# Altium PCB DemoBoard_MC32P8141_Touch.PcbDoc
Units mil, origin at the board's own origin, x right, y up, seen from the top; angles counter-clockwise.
Board outline 4235 x 4095 mil, 2 copper layers (Top Layer, Bottom Layer); 32 components, 31 nets, 87 pads, 28 vias.
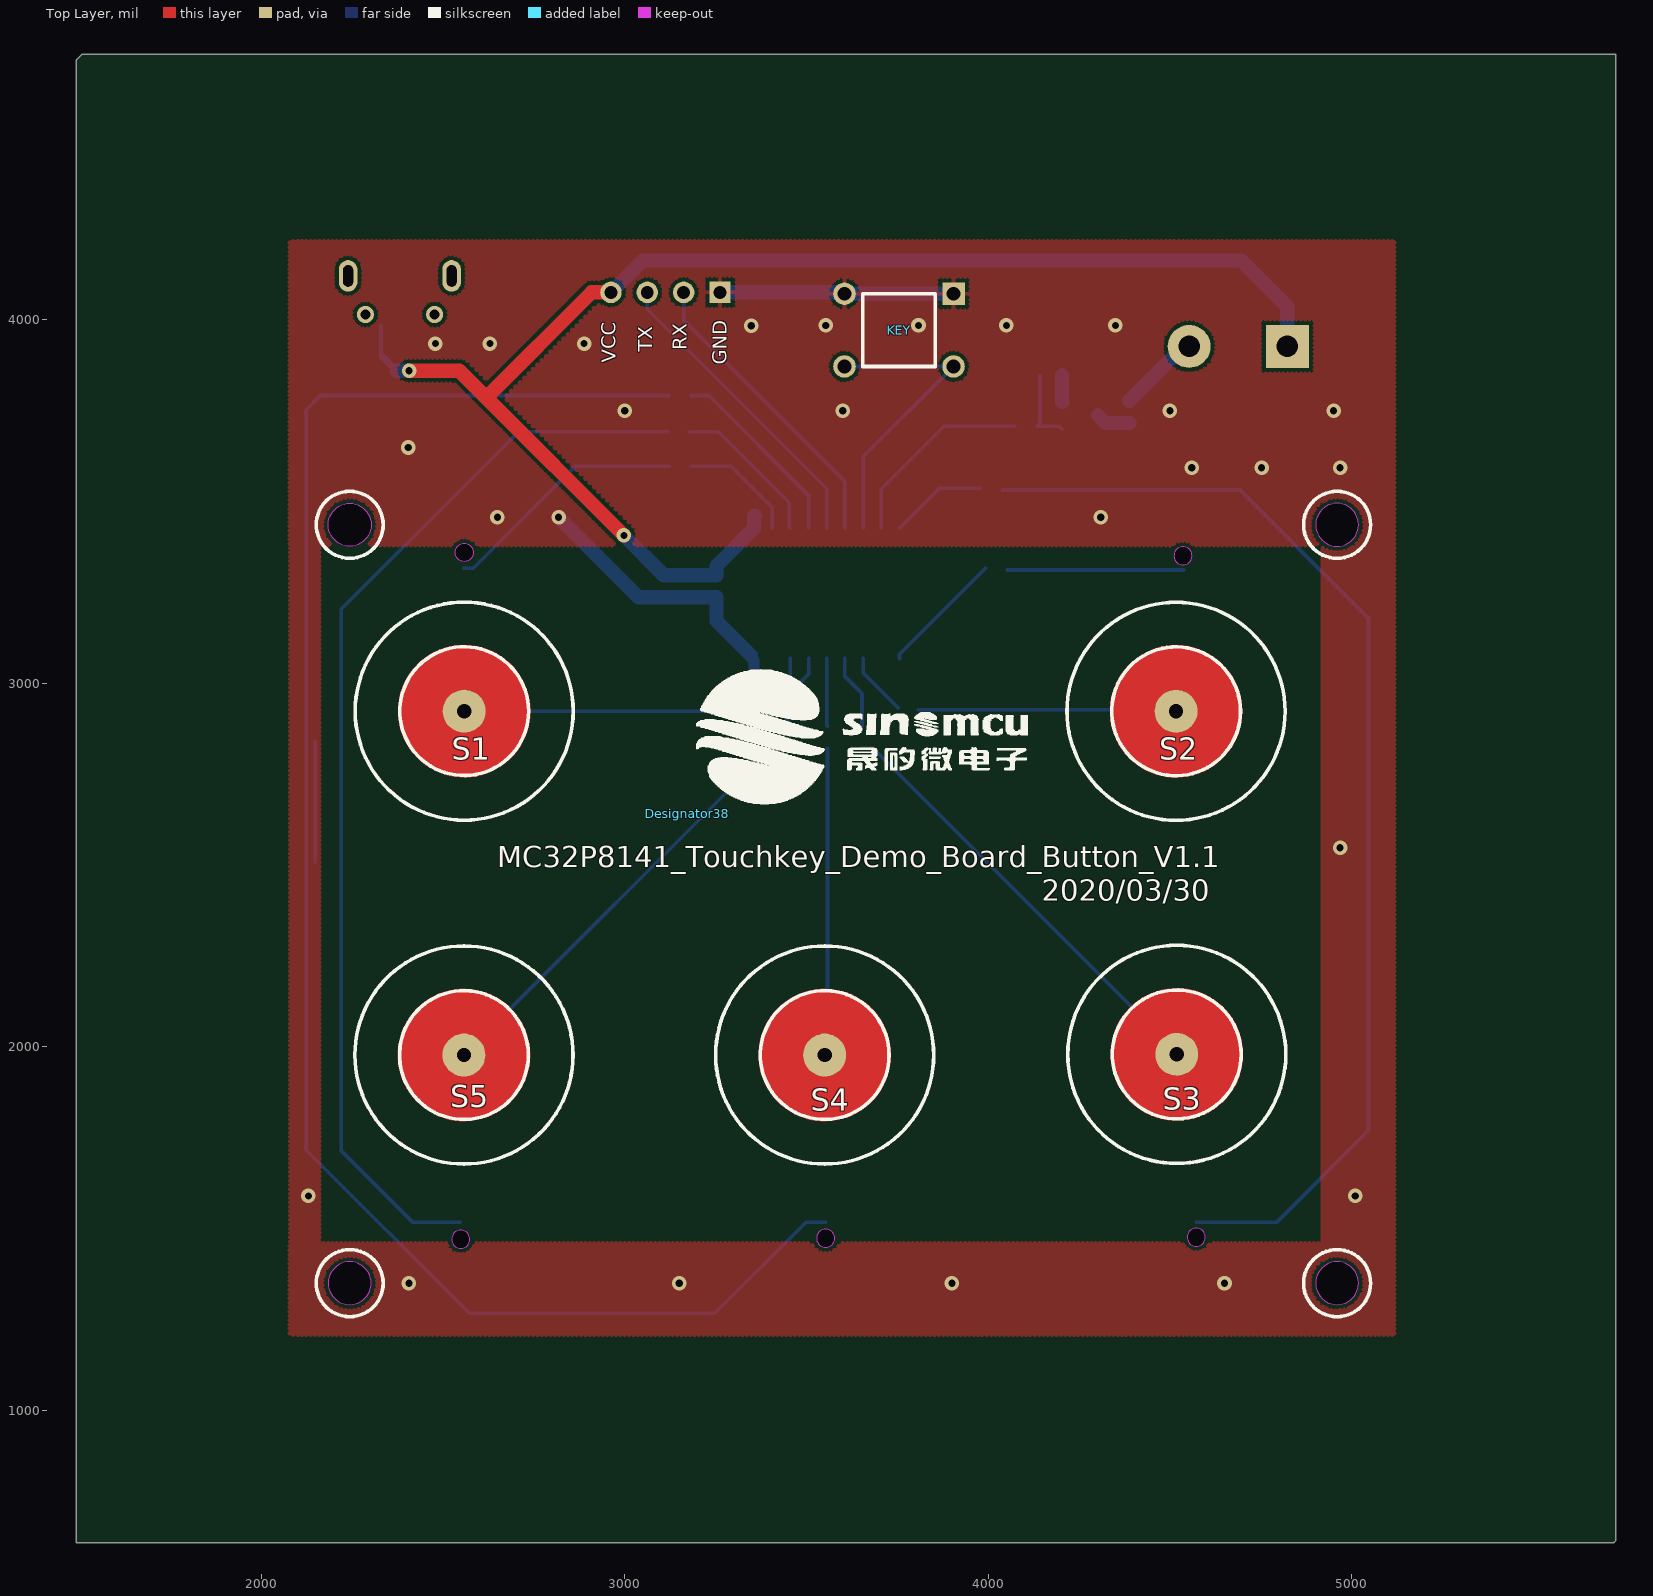
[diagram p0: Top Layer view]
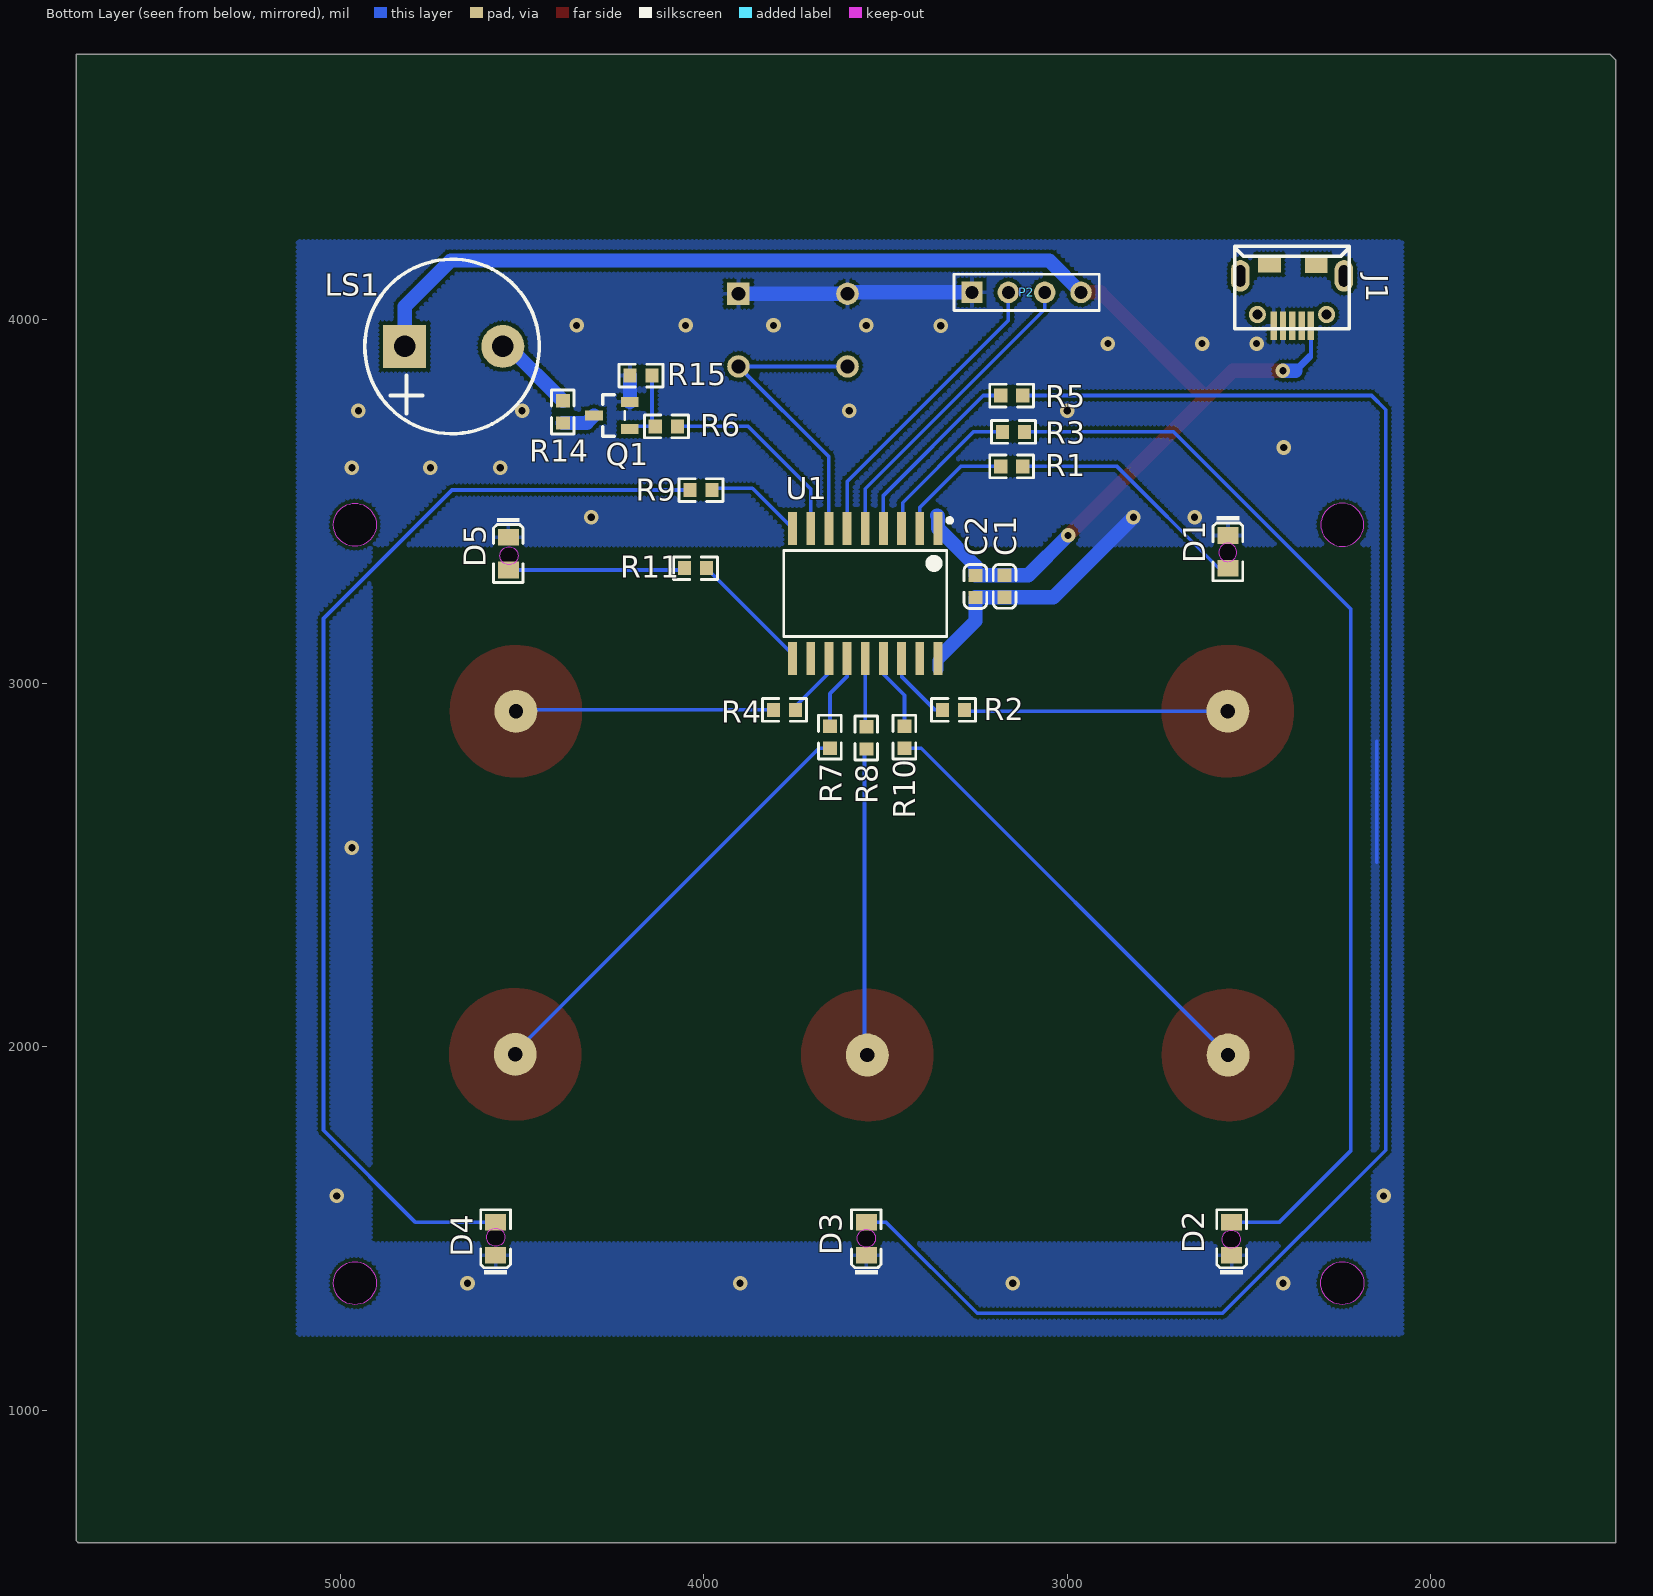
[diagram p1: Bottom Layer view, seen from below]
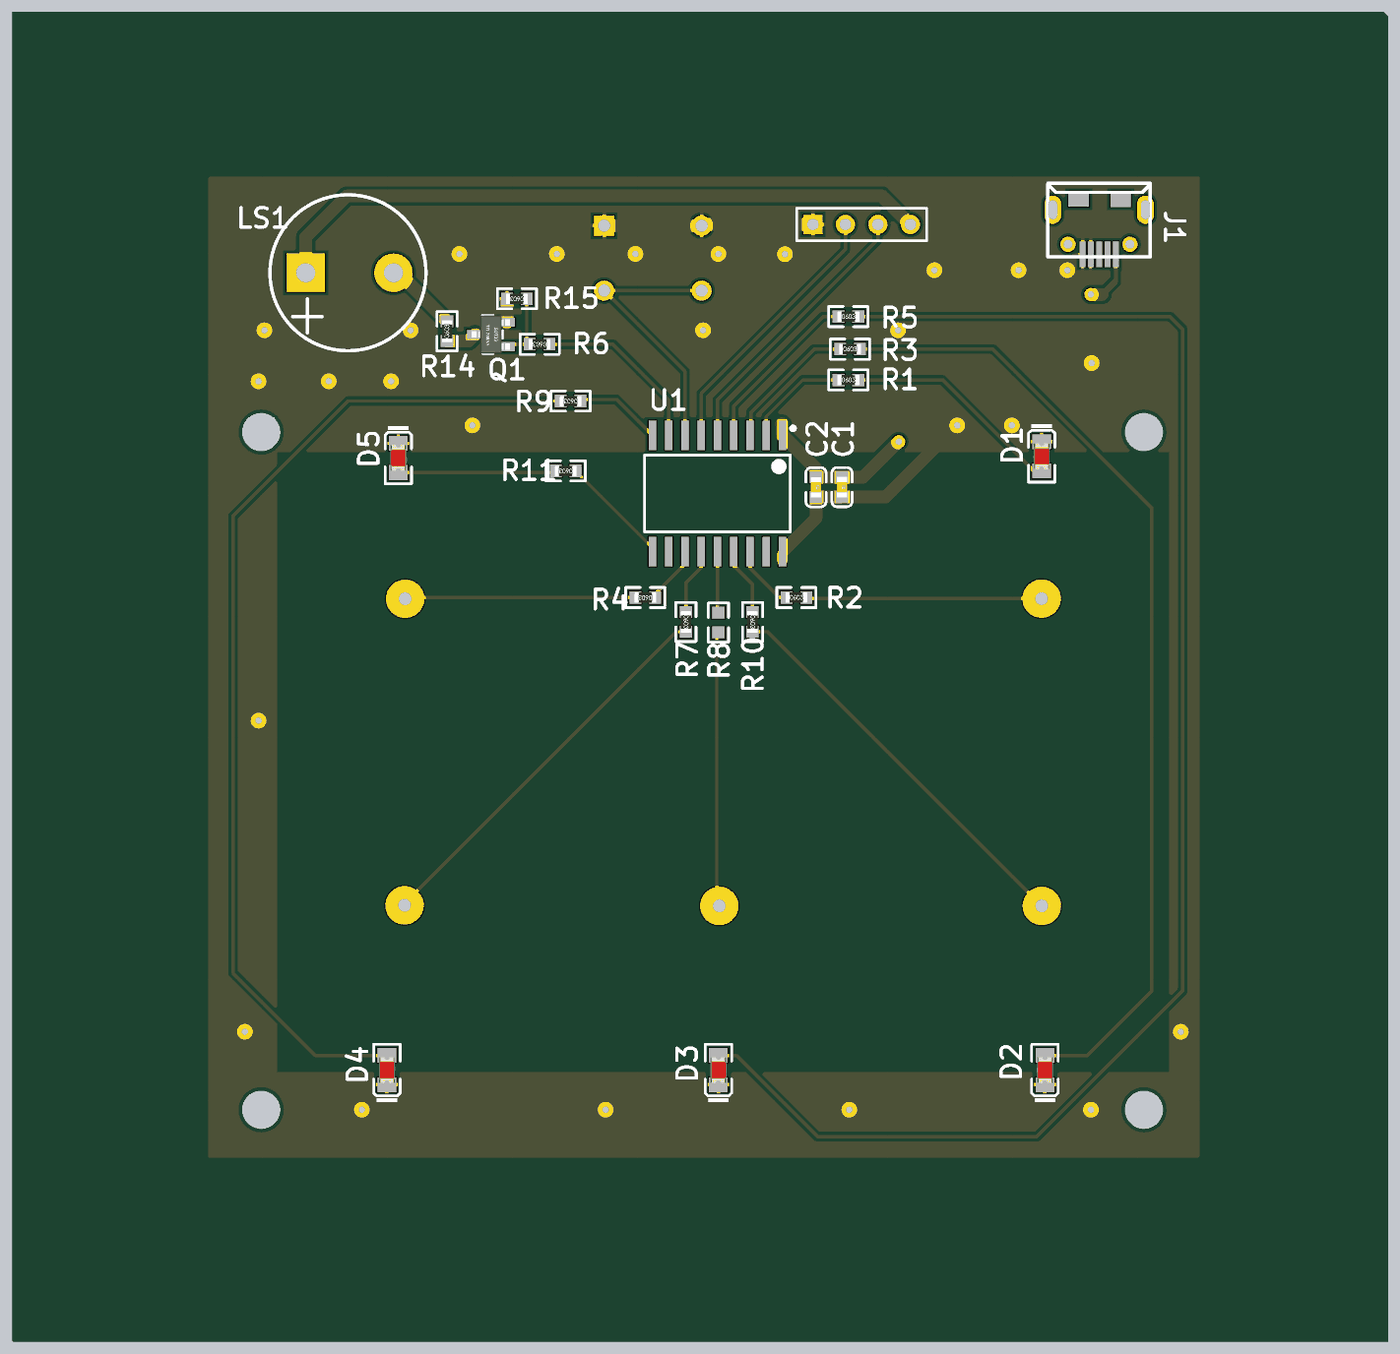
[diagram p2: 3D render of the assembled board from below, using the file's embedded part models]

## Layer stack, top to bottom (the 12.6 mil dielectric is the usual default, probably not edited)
Top Layer: signal copper 1.4
Dielectric: dielectric 12.6, FR-4, Dk 4.8
Bottom Layer: signal copper 1.4

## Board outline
5726.18,4730.67 5726.18,640.67 5721.18,635.67 1491.18,635.67 1491.18,4715.67 1506.18,4730.67
cut-out: 4900.79,3436.42 ccw(c4959.84,3436.42) 4959.84,3377.36 ccw(c4959.84,3436.42) 5018.9,3436.42 ccw(c4959.84,3436.42) 4959.84,3495.47 ccw(c4959.84,3436.42)
cut-out: 4900.79,1349.8 ccw(c4959.84,1349.8) 4959.84,1290.75 ccw(c4959.84,1349.8) 5018.9,1349.8 ccw(c4959.84,1349.8) 4959.84,1408.86 ccw(c4959.84,1349.8)
cut-out: 2523.62,1470.47 ccw(c2548.62,1470.47) 2548.62,1445.47 ccw(c2548.62,1470.47) 2573.62,1470.47 ccw(c2548.62,1470.47) 2548.62,1495.47 ccw(c2548.62,1470.47)
cut-out: 3527.56,1473.43 ccw(c3552.56,1473.43) 3552.56,1448.43 ccw(c3552.56,1473.43) 3577.56,1473.43 ccw(c3552.56,1473.43) 3552.56,1498.43 ccw(c3552.56,1473.43)
cut-out: 4547.24,1476.38 ccw(c4572.24,1476.38) 4572.24,1451.38 ccw(c4572.24,1476.38) 4597.24,1476.38 ccw(c4572.24,1476.38) 4572.24,1501.38 ccw(c4572.24,1476.38)
cut-out: 4510.83,3351.38 ccw(c4535.83,3351.38) 4535.83,3326.38 ccw(c4535.83,3351.38) 4560.83,3351.38 ccw(c4535.83,3351.38) 4535.83,3376.38 ccw(c4535.83,3351.38)
cut-out: 2558.46,3335.24 cw(c2558.46,3360.24) 2533.46,3360.24 cw(c2558.46,3360.24) 2558.46,3385.24 cw(c2558.46,3360.24) 2583.46,3360.24 cw(c2558.46,3360.24)
cut-out: 2243.31,3377.36 cw(c2243.31,3436.42) 2184.25,3436.42 cw(c2243.31,3436.42) 2243.31,3495.47 cw(c2243.31,3436.42) 2302.36,3436.42 cw(c2243.31,3436.42)
cut-out: 2184.25,1349.8 ccw(c2243.31,1349.8) 2243.31,1290.75 ccw(c2243.31,1349.8) 2302.36,1349.8 ccw(c2243.31,1349.8) 2243.31,1408.86 ccw(c2243.31,1349.8)

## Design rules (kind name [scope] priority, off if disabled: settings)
Clearance [All] p1: gap=7
HoleToHoleClearance [All] p1: gap=0 allowstackedmicrovias=TRUE
MinimumSolderMaskSliver [All] p1: minsoldermaskwidth=0
PolygonConnect PolygonConnect_1 [All vs IsVia] p1: connectstyle=Direct reliefconductorwidth=10 reliefentries=4 polygonreliefangle="90 Angle" airgapwidth=10
PolygonConnect [All] p2: connectstyle=Relief reliefconductorwidth=10 reliefentries=4 polygonreliefangle="90 Angle" airgapwidth=10
RoutingVias [All] p1: holewidth=20 width=40 viastyle="Through Hole" minholewidth=10 minwidth=15 maxholewidth=30 maxwidth=60
ShortCircuit [All] p1 off: allowed=FALSE
SilkToSilkClearance [All] p1: silktosilkclearance=0
SilkscreenOverComponentPads SilkToSolderMaskClearance [IsPad] p1: minsilkscreentomaskgap=0
SolderMaskExpansion [All] p1: expansion=4
Width [All] p1: maxlimit=196.85 minlimit=10 preferedwidth=10 bottomlayer_maxwidth=39.37 minimp=50.000000 maximp=50.000000 favimp=50.000000
23 further rules are at their usual default settings.

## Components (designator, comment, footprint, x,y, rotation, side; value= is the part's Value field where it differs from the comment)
C1 "10uF (106) 10% 10V" 0603_C 3172.52,3267.01 r270 bottom
C2 "100nF (104) 10% 50V" 0603_C 3252.52,3266.71 r270 bottom
D1 "蓝灯 0805" 0805_drill_LED 2557.8,3362.01 r270 bottom
D2 "蓝灯 0805" 0805_drill_LED 2547.8,1472.01 r90 bottom
D3 "蓝灯 0805" 0805_drill_LED 3552.8,1472.01 r90 bottom
D4 "蓝灯 0805" 0805_drill_LED 4572.8,1472.01 r90 bottom
D5 "蓝灯 0805" 0805_drill_LED 4537.8,3357.01 r270 bottom
Designator38 "Comment" SINOMCU_LOGO2 3172,2642 r0 top
J1 "MICRO-USB" MICRO-USB-1 2382,4064 r90 bottom
KEY "" KEY_6*6 3904.53,4072.05 r180 top
LS1 "BUZZER" BZ 4552.8,3927.01 r0 bottom
P2 "Header 4" HDR1X4 3262.01,4075.79 r180 bottom
Q1 "SS8050 Y1" SOT-23(SOT-23-3) 4252.8,3737.01 r180 bottom
R1 "1KΩ (1001) ±5%" 0603_R 3152.8,3597.01 r180 bottom
R2 "1KΩ (1001) ±5%" 0603_R 3312.8,2927.01 r180 bottom
R3 "1KΩ (1001) ±5%" 0603_R 3147.8,3692.01 r180 bottom
R4 "1KΩ (1001) ±5%" 0603_R 3777.8,2927.01 r0 bottom
R5 "1KΩ (1001) ±5%" 0603_R 3152.8,3792.01 r180 bottom
R6 "1KΩ (1001) ±5%" 0603_R 4102.8,3707.01 r0 bottom
R7 "1KΩ (1001) ±5%" 0603_R 3652.8,2852.01 r270 bottom
R8 "1KΩ (1001) ±5%" 0603_R 3552.8,2850 r270 bottom
R9 "1KΩ (1001) ±5%" 0603_R 4007.8,3532.01 r0 bottom
R10 "1KΩ (1001) ±5%" 0603_R 3447.8,2852.01 r270 bottom
R11 "1KΩ (1001) ±5%" 0603_R 4022.8,3317.01 r0 bottom
R14 "22Ω (22R0) ±5%" 0603_R 4387.8,3747.01 r90 bottom
R15 "1KΩ (1001) ±5%" 0603_R 4172.8,3847.01 r0 bottom
S1 "TK_Button" TK 2558.27,2923.66 r0 top locked
S2 "TK_Button" TK 4516.73,2923.23 r0 top
S3 "TK_Button" TK 4518.7,1979.33 r0 top
S4 "TK_Button" TK 3550,1977.56 r0 top
S5 "TK_Button" TK 2557.52,1977.56 r0 top locked
U1 "MC32P8141" SOP18 3557.52,3232.01 r0 bottom locked

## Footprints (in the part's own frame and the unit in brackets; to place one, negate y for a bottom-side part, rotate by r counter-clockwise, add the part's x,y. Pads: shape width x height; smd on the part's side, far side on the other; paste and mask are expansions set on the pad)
0603_C [mm]
  rect 0.93x0.98 smd: 1(-0.77,0) 2(0.77,0)
  silkscreen extent -1.53,-0.79 1.54,0.79, body extent -0.8,-0.4 0.8,0.4, height 0.3
0603_R [mm]
  rect 0.93x0.98 smd: 1(-0.77,0) 2(0.77,0)
  silkscreen extent -1.53,-0.79 1.54,0.79, body extent -0.85,-0.4 0.85,0.4, height 0.56
0805_drill_LED [mm]
  rect 1.16x1.47 smd: A(1.144,0) K(-1.144,0)
  silkscreen extent -2.5,-1.04 2.02,1.03, body extent -1.01,-0.63 1.01,0.62, height 1.1
BZ [mm]
  rect 3x3 hole 1.5: 1(6.858,0)
  round 3 hole 1.5: 2(0,0)
  silkscreen extent -2.54,-6.1 9.65,6.1
HDR1X4 [mm] "Connector; Header; 4 Position"
  rect 1.5x1.5 hole 0.9: 1(0,0)
  round 1.5 hole 0.9: 2(2.54,0) 3(5.08,0) 4(7.62,0)
  silkscreen extent -1.27,-1.27 8.89,1.27
KEY_6*6 [mil]
  rect 62x62 hole 38: 1(0,0)
  round 62 hole 38: 2(0,200) 3(300,200) 4(300,0)
  silkscreen extent 50,0 250,200
MICRO-USB-1 [mm]
  round 1.2 hole 0.7: 0(-1.247,-2.43) 0(-1.247,2.411)
  oval 2.2x1.3 hole 0.7 slot 1.5 at 0 deg: 0(1.453,-3.639) 0(1.453,3.6)
  rect 1.2x1.6 smd: 0(2.264,-1.704) 0(2.281,1.576)
  rect 2x0.45 smd: 1(-2.032,-1.33) 2(-2.032,-0.68) 3(-2.032,-0.031) 4(-2.032,0.619) 5(-2.032,1.269)
  silkscreen extent -2.24,-4.02 3.52,3.98
SINOMCU_LOGO2 [mil] "24mmx10mm"
  silkscreen extent 24,27 937,397
SOP18 [mil]
  rect 24x91 smd: 1(-201.8,-194.5) 2(-151.8,-194.5) 3(-101.8,-194.5) 4(-51.8,-194.5) 5(-1.8,-194.5) 6(48.2,-194.5) 7(98.2,-194.5) 8(148.2,-194.5) 9(198.2,-194.5) 10(198.2,163.5) 11(148.2,163.5) 12(98.2,163.5) 13(48.2,163.5) 14(-1.8,163.5) 15(-51.8,163.5) 16(-101.8,163.5) 17(-151.8,163.5) 18(-201.8,163.5)
  silkscreen extent -240,-222 223,103
SOT-23(SOT-23-3) [mm]
  rect 1.25x0.7 smd: 1(1.25,-0.95) 2(1.25,0.95) 3(-1.25,0)
  silkscreen extent -0.65,-1.46 0.9,1.46, body extent -1.5,-1.5 1.5,1.5, height 1.3
TK [mm]
  round 3 hole 1: 1(0,0)
  Top Layer circle w3.175: c0,0 r3.048
  silkscreen extent -7.62,-7.62 7.62,7.62

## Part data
C1: library part "0603 1", "贴?"
C2: library part "0603 10", "贴?"
D1 D2 D3 D4 D5: library part 0, "发?"
J1: library part 1734035-2, "Surface Mount Type B Mini USB, 5 Positions, 0.8 mm Pitch, 0 to 50 degC, RoHS, Tape and Reel"
KEY: library part SW-PB, "Switch"
LS1: "GSD12810YB-3V2400"
P2: "Header, 4-Pin"
Q1: library part "SOT-23 SS", "三?"
R1 R2 R3 R4 R5 R7 R8 R9 R10 R11: library part "0603 1KΩ (100", "?"
R6 R14 R15: library part 0603, "贴?"
U1: library part SOP18

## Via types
v1: diameter 40, hole 20, Top Layer to Bottom Layer, 28 vias

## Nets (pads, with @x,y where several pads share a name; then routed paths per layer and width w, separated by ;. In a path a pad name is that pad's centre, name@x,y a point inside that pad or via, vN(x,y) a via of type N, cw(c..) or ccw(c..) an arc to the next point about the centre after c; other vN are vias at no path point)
GND: C1.2 C2.2 D1.K D2.K D3.K D4.K D5.K J1.4 J1.5 KEY.1 KEY.4 P2.1 Q1.2 R15.2 U1.18 | length 1817.3
  Bottom Layer w10: 2148,2508 2148,2840
  Bottom Layer w30.37: U1.18@3347.44,3076.79 3347.44,3070.87 3355.72,3062.59 U1.18@3355.72,3038.97
  Bottom Layer w39.37: v1(2817.8,3457.01) 3038.11,3236.69 C1.2 3252.22,3236.69 C2.2 3252.52,3171.71 U1.18@3347.44,3076.79 ; P2.1 KEY.4@3608.27,4075.79 ; KEY.4 KEY.1 ; R15.2 4203.11,3774.88 Q1.2
  other v1: 2406.27,1350 3150,1350 3900,1350 4650,1350 2129.77,1590 5010,1590 4968,2548 2649.8,3457.01 4309.8,3457.01 4560,3593 4752,3593 4968,3593 2404,3649 3000,3750 3600,3750 4500,3750 4950,3750 2479,3935 2629,3935 2887.94,3935 3348,3984.29 3552.8,3984.99 3808.11,3984.99 4050,3984.99 4350,3984.99
NetD1_A: D1.A R1.2 | length 680.7
  Bottom Layer w10: D1.A 2582.76,3316.97 2862.8,3597.01 R1.2
NetD2_A: D2.A R3.2 | length 2999.4
  Bottom Layer w10: D2.A 2417.09,1517.05 2219.53,1714.61 2219.53,3203.74 2707.8,3692.01 R3.2
NetD3_A: D3.A R5.2 | length 4770.2
  Bottom Layer w10: R5.2 2162.8,3792.01 2124.02,3753.23 2124.02,1715.79 2572.8,1267.01 3247.8,1267.01 3497.83,1517.05 D3.A
NetD4_A: D4.A R9.2 | length 3141.1
  Bottom Layer w10: R9.2 4692.8,3532.01 5046.26,3178.54 5046.26,1770.47 4792.83,1517.05 D4.A
NetD5_A: D5.A R11.2 | length 484.7
  Bottom Layer w10: R11.2@4053.11,3311.97 D5.A
NetLS1_2: LS1.2 R14.2 | length 227
  Bottom Layer w39.37: R14.2 4537.48,3927.01 LS1.2
NetQ1_1: Q1.1 R6.2 R15.1 | length 217.4
  Bottom Layer w10: R15.1 4142.48,3716.38 R6.2 4196.18,3707.01 Q1.1
NetQ1_3: Q1.3 R14.1 | length 94.2
  Bottom Layer w39.37: Q1.3 4322.32,3716.69 R14.1
NetR2_2: R2.2 S1.1 | length 725.6
  Bottom Layer w10: S1.1 3279.13,2923.66 R2.2
NetR4_2: R4.2 S2.1 | length 720
  Bottom Layer w10: R4.2 4523.43,2927.01 S2.1@4526.77,2923.66
NetR7_2: R7.2 S3.1 | length 1224.9
  Bottom Layer w10: R7.2 3683.11,2821.69 S3.1@4527.8,1977.01
NetR8_2: R8.2 S4.1 | length 850.8
  Bottom Layer w10: S4.1@3541.77,1977.56 3557.8,1993.58 R8.2@3557.8,2821.69
NetR10_2: R10.2 S5.1 | length 1239.9
  Bottom Layer w10: S5.1 3401.65,2821.69 R10.2
P00: R3.1 U1.3 | length 427.2
  Bottom Layer w10: R3.1 3257.8,3692.01 3452.8,3497.01 3452.8,3429.43 U1.3
P01: R5.1 U1.4 | length 527
  Bottom Layer w10: R5.1 3230.72,3792.01 3505.72,3517.01 U1.4
P02: P2.3 U1.5 | length 853.8
  Bottom Layer w10: P2.3 3062.01,4029.53 3555.72,3535.82 U1.5
P03: P2.2 U1.6 | length 833.1
  Bottom Layer w10: P2.2 3162.01,3998.43 3605.72,3554.71 U1.6
P04: KEY.2 KEY.3 U1.7 | length 848.6
  Bottom Layer w10: KEY.3 KEY.2 3655.72,3623.24 U1.7
P05: R6.1 U1.8 | length 546.5
  Bottom Layer w10: U1.8 3705.72,3534.93 3877.8,3707.01 R6.1
P06: R9.1 U1.9 | length 267.5
  Bottom Layer w10: U1.9 3866.22,3537.01 R9.1@3977.48,3537.01
P07: R11.1 U1.10 | length 346.6
  Bottom Layer w10: U1.10 3755.72,3080.25 R11.1
P10: U1.11
P11: R4.1 U1.12 | length 176.5
  Bottom Layer w10: U1.12 3655.72,3029.08 R4.1@3752.64,2932.16
P12: R7.1 U1.13 | length 205.7
  Bottom Layer w10: U1.13 3605.72,3019.08 3652.8,2972.01 R7.1
P13: R8.1 U1.14 | length 187
  Bottom Layer w10: U1.14 3555.72,2884.4 R8.1@3557.8,2882.32
P14: R10.1 U1.15 | length 210.2
  Bottom Layer w10: R10.1 3447.8,2967.01 3505.72,3024.93 U1.15
P15: R2.1 U1.16 | length 200.4
  Bottom Layer w10: R2.1 3364.02,2927.01 3455.72,3018.71 U1.16
P16: U1.17
P17: R1.1 U1.2 | length 327
  Bottom Layer w10: R1.1 3292.8,3597.01 3405.72,3484.08 U1.2
VCC: C1.1 C2.1 J1.1 LS1.1 P2.4 U1.1 | length 3986.4
  Top Layer w39.37: v1(2406.5,3860.24) 2544.57,3860.24 2618.74,3786.06 ; P2.4 2908.46,4075.79 2618.74,3786.06 ; v1(2997.8,3407.01) 2618.74,3786.06
  Bottom Layer w11.81: J1.1@2329.52,3983.97 2329.52,3902.76 2333.7,3898.59
  Bottom Layer w19.68: 2333.7,3898.59 2372.05,3860.24
  Bottom Layer w39.37: 2372.05,3860.24 v1(2406.5,3860.24) ; P2.4 3049.61,4163.39 4696.42,4163.39 4822.8,4037.01 LS1.1 ; v1(2997.8,3407.01) 3107.48,3297.32 C1.1 3252.22,3297.32 C2.1 3252.52,3323.31 U1.1 3355.72,3459.93 U1.1@3357.8,3462.01
pads on no net: J1.0 J1.2 J1.3

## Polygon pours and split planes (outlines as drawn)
no net on Bottom Layer "Bottom Layer-No Net 7" (solid, pour order 4): 2222.8,3342.01
GND on Bottom Layer "Top Layer-No Net" (hatched 90Degree grid 12 track 12, remove dead copper, pour order 19): 2077.8,4217.01 2160,4217.01 2160,3960 2160,2670 2160,1977.56 2160,1208.07 2077.8,1208.07 2077.8,4217.01
GND on Bottom Layer "Top Layer-No Net" (hatched 90Degree grid 12 track 12, remove dead copper, pour order 21): 4920,4217.01 4916.22,4213.23 4916.22,3961.77 4916.22,2671.77 4916.22,1979.33 4916.22,1211.85 4920,1208.07 5117.32,1208.07 5117.32,4217.01 4920,4217.01
GND on Bottom Layer "Top Layer-No Net" (hatched 90Degree grid 12 track 12, remove dead copper, pour order 35): 2077.8,1208.07 2077.8,1460 5117.32,1460 5117.32,1208.07 2077.8,1208.07
GND on Bottom Layer "Top Layer-No Net" (hatched 90Degree grid 12 track 12, remove dead copper, pour order 39): 2077.8,4217.01 2077.8,3380 5117.32,3380 5117.32,4217.01 2077.8,4217.01
GND on Top Layer "GND_L02_P-001" (solid, remove dead copper, pour order 54): 4217.8,3627.01
GND on Top Layer "GND_L02_P-001" (solid, remove dead copper, pour order 52): 4297.8,3707.01
GND on Top Layer "GND_L02_P-001" (solid, remove dead copper, pour order 48): 4227.8,3547.01
GND on Top Layer "Top Layer-No Net" (hatched 90Degree grid 12 track 12, remove dead copper, pour order 23): 2077.8,4217.01 2157.01,4217.01 2160,4220 2160,3960 2160,2670 2160,1977.56 2160,1208.07 2080,1208.07 2080,4214.8 2077.8,4217.01
GND on Top Layer "Top Layer-No Net" (hatched 90Degree grid 12 track 12, remove dead copper, pour order 25): 4920,4217.01 4920,1208.07 5117.32,1208.07 5117.32,4217.01 4920,4217.01
GND on Top Layer "Top Layer-No Net" (hatched 90Degree grid 12 track 12, remove dead copper, pour order 37): 2077.8,1208.07 2077.8,1460 5117.32,1460 5117.32,1208.07 2077.8,1208.07
GND on Top Layer "Top Layer-No Net" (hatched 90Degree grid 12 track 12, remove dead copper, pour order 41): 2077.8,4217.01 5117.32,4217.01 5117.32,3380 2077.8,3380 2077.8,4217.01

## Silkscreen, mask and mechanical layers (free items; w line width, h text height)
Top Overlay:
  circle w10: c2243.31,1349.8 r92.2
  circle w10: c4959.84,1349.8 r92.2
  circle w10: c4959.84,3436.42 r92.2
  circle w10: c2243.31,3436.42 r92.2
  text "RX" at 3170.04,3916.85 h39.37 r90
  text "TX" at 3075.04,3912.06 h39.37 r90
  text "VCC" at 2975.04,3881.85 h39.37 r90
  text "GND" at 3280.04,3876.85 h39.37 r90
  text "MC32P8141_Touchkey_Demo_Board_Button_V1.1" at 2648.62,2475.39 h100
  text "2020/03/30" at 4147.64,2382.87 h100
Mechanical 1:
  circle w10: c4959.84,3436.42 r59.06
  circle w10: c4959.84,1349.8 r59.06
  circle w10: c2243.31,1349.8 r59.06
  circle w3.94: c2548.62,1470.47 r25
  circle w3.94: c3552.56,1473.43 r25
  circle w3.94: c4572.24,1476.38 r25
  circle w3.94: c4535.83,3351.38 r25
  circle w3.94: c2558.46,3360.24 r25
  circle w10: c2243.31,3436.42 r59.06
  lines w10: 2077.8,1208.07 2077.8,4217.01 5117.32,4217.01 5117.32,1208.07 2077.8,1208.07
